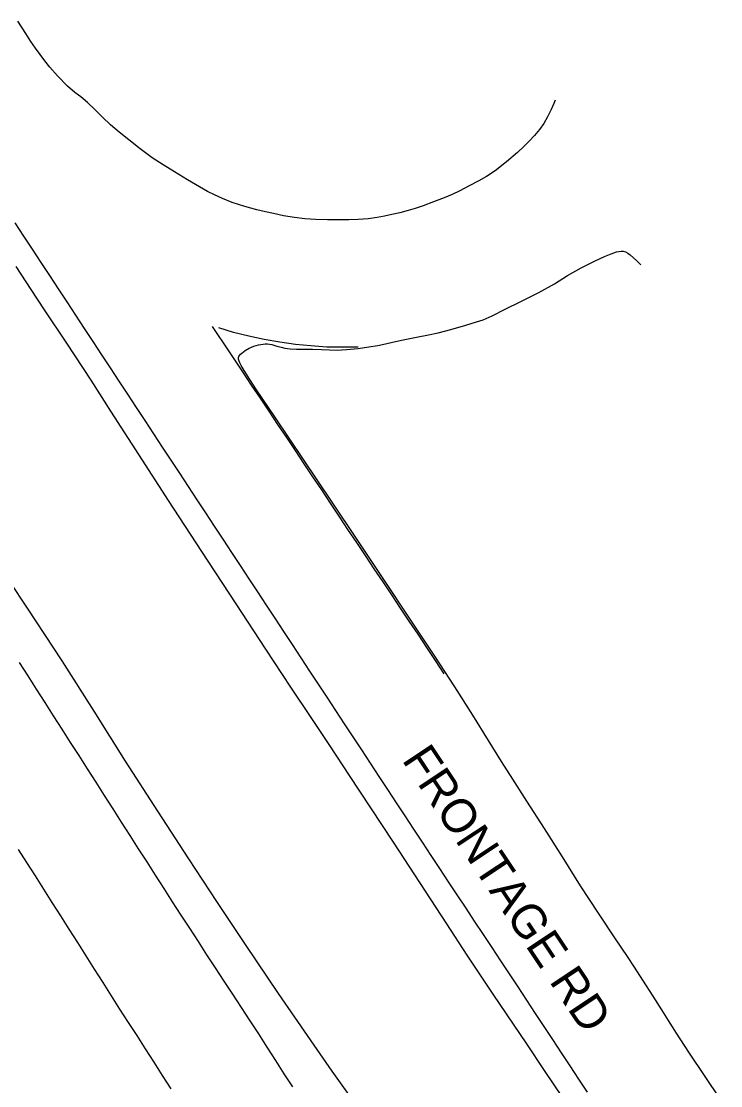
# Model space of a CAD drawing. Extents: x 1948091 to 1975253, y 787267 to 823306.
# Drawn here: x 1969427.3 to 1969538.1, y 798356.6 to 798525.4 of the extents above; entities that cross this region are included whole.
import ezdxf

# ---------------------------------------------------------------- set-up
doc = ezdxf.new("R2010")
doc.units = 0
for name, color, linetype in [('RD_EX_Pavement_Markings', 7, 'Continuous'), ('RD_EX_Road', 7, 'Continuous'), ('RD_TX_RoadID', 7, 'Continuous')]:
    doc.layers.add(name, color=color, linetype=linetype)

msp = doc.modelspace()

# ---------------------------------------------------------------- linework, layer by layer
at = {"layer": 'RD_EX_Pavement_Markings'}
for points in [[(1969517, 798355.58), (1969515.62, 798357.66), (1969514.25, 798359.75), (1969512.87, 798361.84), (1969511.5, 798363.92), (1969510.12, 798366.01), (1969508.75, 798368.09), (1969507.37, 798370.18), (1969506, 798372.27), (1969504.62, 798374.35), (1969503.25, 798376.44), (1969501.87, 798378.53), (1969500.5, 798380.61), (1969499.12, 798382.7), (1969497.75, 798384.79), (1969496.37, 798386.88), (1969495, 798388.96), (1969493.62, 798391.05), (1969492.25, 798393.14), (1969490.87, 798395.22), (1969489.5, 798397.31), (1969488.12, 798399.4), (1969486.75, 798401.49), (1969485.37, 798403.57), (1969484, 798405.66), (1969482.62, 798407.75), (1969481.25, 798409.84), (1969479.87, 798411.92), (1969478.5, 798414.01), (1969477.12, 798416.1), (1969475.75, 798418.19), (1969474.38, 798420.28), (1969473, 798422.36), (1969471.63, 798424.45), (1969470.26, 798426.54), (1969468.88, 798428.63), (1969467.51, 798430.72), (1969466.14, 798432.81), (1969464.76, 798434.9), (1969463.39, 798436.99), (1969462.01, 798439.07), (1969460.64, 798441.16), (1969459.27, 798443.25), (1969457.89, 798445.34), (1969456.52, 798447.43), (1969455.15, 798449.52), (1969453.77, 798451.61), (1969452.4, 798453.7), (1969451.03, 798455.78), (1969449.65, 798457.87), (1969448.28, 798459.96), (1969446.91, 798462.05), (1969445.54, 798464.14), (1969444.16, 798466.23), (1969442.79, 798468.32), (1969441.42, 798470.41), (1969440.05, 798472.5), (1969438.67, 798474.59), (1969437.3, 798476.68), (1969435.93, 798478.77), (1969434.56, 798480.86), (1969433.19, 798482.95), (1969431.81, 798485.04), (1969430.44, 798487.13), (1969429.07, 798489.22), (1969427.7, 798491.31), (1969426.33, 798493.4)], [(1969494.31, 798421.94), (1969492.92, 798424.02), (1969491.54, 798426.1), (1969490.15, 798428.18), (1969488.76, 798430.26), (1969487.38, 798432.34), (1969485.99, 798434.42), (1969484.6, 798436.5), (1969483.22, 798438.58), (1969481.83, 798440.66), (1969480.44, 798442.74), (1969479.05, 798444.82), (1969477.67, 798446.9), (1969476.28, 798448.98), (1969474.89, 798451.06), (1969473.5, 798453.14), (1969472.12, 798455.22), (1969470.73, 798457.3), (1969469.34, 798459.38), (1969467.96, 798461.46), (1969466.57, 798463.53), (1969465.18, 798465.61), (1969463.79, 798467.69), (1969462.41, 798469.77), (1969461.02, 798471.85), (1969459.63, 798473.93), (1969458.24, 798476.01), (1969457.61, 798476.97)], [(1969480.66, 798473.72), (1969478.17, 798473.68), (1969475.68, 798473.72), (1969473.19, 798473.89), (1969470.71, 798474.11), (1969468.24, 798474.47), (1969465.79, 798474.93), (1969463.34, 798475.42), (1969460.93, 798476.05), (1969458.57, 798476.78)], [(1969426.98, 798423.69), (1969428.32, 798421.59), (1969429.67, 798419.48), (1969431.01, 798417.37), (1969432.36, 798415.27), (1969433.71, 798413.16), (1969435.05, 798411.05), (1969436.4, 798408.95), (1969437.74, 798406.84), (1969439.09, 798404.73), (1969440.43, 798402.62), (1969441.78, 798400.52), (1969443.12, 798398.41), (1969444.47, 798396.3), (1969445.81, 798394.19), (1969447.16, 798392.09), (1969448.5, 798389.98), (1969449.85, 798387.87), (1969451.2, 798385.77), (1969452.56, 798383.68), (1969453.93, 798381.58), (1969455.3, 798379.49), (1969456.66, 798377.39), (1969458.03, 798375.3), (1969459.39, 798373.2), (1969460.76, 798371.11), (1969462.12, 798369.02), (1969463.49, 798366.92), (1969464.85, 798364.83), (1969466.21, 798362.73), (1969467.56, 798360.62), (1969468.91, 798358.52), (1969470.26, 798356.42)], [(1969451.05, 798356.15), (1969449.69, 798358.25), (1969448.34, 798360.36), (1969446.99, 798362.46), (1969445.63, 798364.56), (1969444.28, 798366.66), (1969442.93, 798368.77), (1969441.59, 798370.88), (1969440.25, 798372.99), (1969438.91, 798375.1), (1969437.57, 798377.21), (1969436.23, 798379.32), (1969434.89, 798381.43), (1969433.55, 798383.54), (1969432.21, 798385.65), (1969430.87, 798387.76), (1969429.53, 798389.87), (1969428.19, 798391.98), (1969426.85, 798394.09)]]:
    msp.add_lwpolyline(points, dxfattribs=at)
at = {"layer": 'RD_EX_Road'}
for points in [[(1969511.88, 798512.88), (1969511.66, 798512.34), (1969511.22, 798511.37), (1969510.65, 798510.23), (1969510.06, 798509.17), (1969509.38, 798508.19), (1969508.58, 798507.24), (1969507.74, 798506.37), (1969506.96, 798505.57), (1969505.89, 798504.57), (1969504.17, 798503.1), (1969502.36, 798501.67), (1969501.01, 798500.76), (1969499.76, 798500.07), (1969498.27, 798499.27), (1969496.78, 798498.5), (1969495.57, 798497.92), (1969494.29, 798497.38), (1969492.62, 798496.73), (1969490.96, 798496.12), (1969489.7, 798495.68), (1969488.56, 798495.34), (1969487.27, 798495), (1969485.99, 798494.71), (1969484.86, 798494.46), (1969483.67, 798494.26), (1969482.23, 798494.07), (1969480.69, 798493.94), (1969479.21, 798493.88), (1969477.63, 798493.87), (1969475.81, 798493.87), (1969473.93, 798493.93), (1969472.22, 798494.04), (1969470.56, 798494.24), (1969468.84, 798494.54), (1969467.25, 798494.87), (1969465.98, 798495.14), (1969464.6, 798495.49), (1969462.69, 798496.02), (1969460.72, 798496.65), (1969459.15, 798497.25), (1969457.89, 798497.84), (1969456.8, 798498.4), (1969455.51, 798499.13), (1969453.62, 798500.24), (1969451.56, 798501.47), (1969449.77, 798502.58), (1969448.04, 798503.74), (1969446.15, 798505.15), (1969444.33, 798506.57), (1969442.78, 798507.8), (1969441.43, 798508.97), (1969440.18, 798510.17), (1969438.97, 798511.37), (1969437.76, 798512.5), (1969436.74, 798513.38), (1969436.36, 798513.66), (1969435.76, 798514.05), (1969434.64, 798515.06), (1969433.05, 798516.69), (1969431.81, 798518.07), (1969431.02, 798519.11), (1969430.29, 798520.11), (1969429.56, 798521.11), (1969428.83, 798522.17), (1969428.01, 798523.42), (1969426.72, 798525.36)], [(1969538.1, 798354.38), (1969533.05, 798361.96), (1969531.12, 798364.96), (1969529.85, 798366.96), (1969528.76, 798368.67), (1969527.38, 798370.81), (1969525.75, 798373.36), (1969524.42, 798375.43), (1969523.32, 798377.11), (1969521.44, 798379.92), (1969518.74, 798383.95), (1969515.89, 798388.33), (1969513.02, 798392.88), (1969510.16, 798397.4), (1969507.4, 798401.74), (1969505.16, 798405.24), (1969503.39, 798408.01), (1969501.31, 798411.33), (1969498.81, 798415.38), (1969495.98, 798419.83), (1969492.8, 798424.71), (1969489.02, 798430.42), (1969484.71, 798436.88), (1969480.5, 798443.2), (1969476.42, 798449.31), (1969471.99, 798455.9), (1969467.44, 798462.65), (1969464.45, 798467.12), (1969463.13, 798469.14), (1969462.43, 798470.26), (1969462.13, 798470.8), (1969461.93, 798471.19), (1969461.81, 798471.5), (1969461.72, 798471.79), (1969461.7, 798471.93), (1969461.7, 798472.07), (1969461.76, 798472.22), (1969461.87, 798472.39), (1969462.03, 798472.57), (1969462.23, 798472.76), (1969462.76, 798473.15), (1969463.41, 798473.54), (1969464.13, 798473.85), (1969464.88, 798474.08), (1969465.59, 798474.2), (1969465.94, 798474.22), (1969466.28, 798474.22), (1969466.64, 798474.17), (1969467.01, 798474.1), (1969467.79, 798473.87), (1969468.46, 798473.69), (1969469.06, 798473.55), (1969469.88, 798473.46), (1969470.89, 798473.39), (1969471.73, 798473.37), (1969472.42, 798473.39), (1969473.45, 798473.38), (1969474.85, 798473.33), (1969476.14, 798473.29), (1969477.33, 798473.25), (1969478.84, 798473.33), (1969480.68, 798473.51), (1969482.35, 798473.74), (1969483.79, 798473.99), (1969485, 798474.23), (1969486.12, 798474.48), (1969487.77, 798474.84), (1969489.93, 798475.28), (1969491.8, 798475.65), (1969493.35, 798475.97), (1969495.34, 798476.49), (1969497.7, 798477.18), (1969499.4, 798477.69), (1969500.45, 798478.02), (1969501.91, 798478.68), (1969503.95, 798479.7), (1969506.46, 798480.94), (1969509.31, 798482.35), (1969511.78, 798483.73), (1969513.85, 798485.05), (1969515.97, 798486.25), (1969518.11, 798487.32), (1969519.71, 798488.07), (1969520.73, 798488.5), (1969521.57, 798488.79), (1969521.95, 798488.89), (1969522.31, 798488.94), (1969522.66, 798488.91), (1969523.02, 798488.8), (1969523.37, 798488.61), (1969523.77, 798488.33), (1969524.8, 798487.4), (1969525.43, 798486.76)], [(1969513.12, 798354.67), (1969510.2, 798359.02), (1969507.36, 798363.24), (1969502.05, 798371.13), (1969497.95, 798377.31), (1969494.72, 798382.27), (1969489.65, 798390.04), (1969486.25, 798395.23), (1969482.67, 798400.68), (1969479.3, 798405.79), (1969476.15, 798410.56), (1969473.22, 798414.99), (1969470.02, 798419.82), (1969466.06, 798425.82), (1969461.36, 798432.99), (1969455.91, 798441.31), (1969450.64, 798449.39), (1969446.48, 798455.79), (1969441.5, 798463.58), (1969438.38, 798468.49), (1969434.53, 798474.32), (1969430.99, 798479.6), (1969428.84, 798482.86), (1969426.46, 798486.48)], [(1969425.43, 798436.55), (1969428.24, 798432.33), (1969433.71, 798424), (1969438.78, 798415.97), (1969443.74, 798408.08), (1969448.85, 798400.13), (1969453.79, 798392.56), (1969458.22, 798385.8), (1969462.76, 798378.98), (1969468, 798371.25), (1969473.65, 798363.06), (1969476.51, 798358.95), (1969479.4, 798354.84)]]:
    msp.add_lwpolyline(points, dxfattribs=at)

# ---------------------------------------------------------------- texts
at = {"layer": 'RD_TX_RoadID'}
msp.add_text('FRONTAGE RD', height=5.4, rotation=303.6489, dxfattribs=at).set_placement((1969487.49, 798408.27))

doc.saveas('drawing.dxf')
